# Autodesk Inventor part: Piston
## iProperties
Shininess: 64.0
Angle Display Precision: 2
Document Length Units: 11272
Document Angle Units: 11279
Document Time Units: 11290
Document Mass Units: 11286
Document Length Units Precision: 3
Document Angle Units Precision: 2
Created: 2006-10
Part Number: Piston
Document SubType Name: Modeling
Designer: John Croya
Density: 1 g/cm^3
Density: 0.0
Volumn: 0.0
Area: 0.0
PropertySet Name: Model Information
Control State: 0
Master: False
Checked Out: False
Author: John Croya
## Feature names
1. Revolution1
